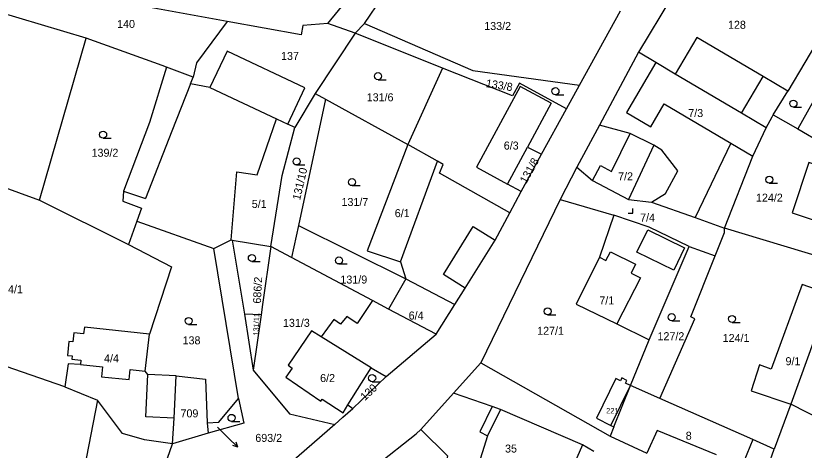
# Model space of a CAD drawing. Extents: x -747333 to -743907, y -1134120 to -1130051.
# Drawn here: x -746528 to -746360.5, y -1132038.3 to -1131946.1 of the extents above; entities that cross this region are included whole.
import ezdxf

# ---------------------------------------------------------------- set-up
doc = ezdxf.new("R2010")
doc.units = 0
for name, color, linetype in [('Hranice parcel', 7, 'Continuous'), ('Parcelní čísla', 7, 'Continuous'), ('Pop  PČ popisy', 7, 'Continuous'), ('Vnitřní kresba', 7, 'Continuous'), ('Značky kultur', 7, 'Continuous')]:
    doc.layers.add(name, color=color, linetype=linetype)

msp = doc.modelspace()

# ---------------------------------------------------------------- linework, layer by layer
at = {"layer": 'Hranice parcel'}
for p, q in [((-746453.89, -1131947.67), (-746438.95, -1131925.52)), ((-746381.8, -1131930.69), (-746395.75, -1131953.81)), ((-746483.07, -1131947.25), (-746560.7, -1131933.13)), ((-746461.71, -1131947.7), (-746454.36, -1131938.7)), ((-746408.25, -1131960.77), (-746399.53, -1131945)), ((-746483.07, -1131947.25), (-746489.62, -1131956.07)), ((-746467.34, -1131950.11), (-746483.07, -1131947.25)), ((-746455.89, -1131949.78), (-746461.71, -1131947.7)), ((-746455.89, -1131949.78), (-746453.89, -1131947.67)), ((-746455.89, -1131949.78), (-746464.41, -1131962.54)), ((-746437.32, -1131957.2), (-746455.89, -1131949.78)), ((-746522.94, -1131985.19), (-746513.04, -1131950.81)), ((-746356.8, -1131949.89), (-746364, -1131962.05)), ((-746352.16, -1131952.55), (-746361.91, -1131970.09)), ((-746466.6, -1131961.34), (-746483.11, -1131953.58)), ((-746395.75, -1131953.81), (-746404.04, -1131969.28)), ((-746489.62, -1131956.07), (-746490.28, -1131959.09)), ((-746490.28, -1131959.09), (-746495.93, -1131956.95)), ((-746437.32, -1131957.2), (-746444.69, -1131973.38)), ((-746411.04, -1131965.81), (-746408.25, -1131960.77)), ((-746464.41, -1131962.54), (-746468.74, -1131969.75)), ((-746464.41, -1131962.54), (-746462.22, -1131963.75)), ((-746367.12, -1131967.06), (-746364, -1131962.05)), ((-746462.22, -1131963.75), (-746467.95, -1131990.55)), ((-746462.22, -1131963.75), (-746444.69, -1131973.38)), ((-746416.31, -1131975.44), (-746411.04, -1131965.81)), ((-746368.62, -1131969.86), (-746367.37, -1131967.53)), ((-746367.37, -1131967.53), (-746367.12, -1131967.06)), ((-746367.12, -1131967.06), (-746361.91, -1131970.09)), ((-746404.04, -1131969.28), (-746408.81, -1131978.18)), ((-746361.91, -1131970.09), (-746334.41, -1131986.06)), ((-746552.82, -1131974.44), (-746522.94, -1131985.19)), ((-746444.69, -1131973.38), (-746453.36, -1131995.97)), ((-746420.64, -1131983.36), (-746416.31, -1131975.44)), ((-746408.81, -1131978.18), (-746412.35, -1131985.06)), ((-746408.81, -1131978.18), (-746405.47, -1131981.01)), ((-746420.64, -1131983.36), (-746423.54, -1131981.79)), ((-746423.09, -1131987.89), (-746420.64, -1131983.36)), ((-746522.94, -1131985.19), (-746504, -1131994.6)), ((-746412.35, -1131985.06), (-746429.19, -1132019.77)), ((-746412.35, -1131985.06), (-746400.99, -1131988.36)), ((-746502.27, -1131989.69), (-746504, -1131994.6)), ((-746502.27, -1131989.69), (-746485.89, -1131995.45)), ((-746400.99, -1131988.36), (-746404.05, -1131997.34)), ((-746467.95, -1131990.55), (-746469.41, -1131997.4)), ((-746467.95, -1131990.55), (-746445.14, -1132001.9)), ((-746354.34, -1131998.17), (-746377.47, -1131991.14)), ((-746485.89, -1131995.45), (-746482.26, -1131993.62)), ((-746482.26, -1131993.62), (-746481.99, -1131993.67)), ((-746481.99, -1131993.67), (-746473.83, -1131995.06)), ((-746481.99, -1131993.67), (-746479.42, -1132009.41)), ((-746480.65, -1132027.32), (-746485.89, -1131995.45)), ((-746469.41, -1131997.4), (-746473.83, -1131995.06)), ((-746393.46, -1132014.85), (-746384.98, -1131995.05)), ((-746384.98, -1131995.05), (-746379.47, -1131997)), ((-746452.2, -1132006.5), (-746469.41, -1131997.4)), ((-746445.14, -1132001.9), (-746448.81, -1132008.32)), ((-746445.14, -1132001.9), (-746434.75, -1132007.36)), ((-746448.81, -1132008.32), (-746452.2, -1132006.5)), ((-746438.69, -1132013.68), (-746448.81, -1132008.32)), ((-746438.69, -1132013.68), (-746434.75, -1132007.36)), ((-746475.88, -1132009.57), (-746479.42, -1132009.41)), ((-746479.42, -1132009.41), (-746477.54, -1132021.27)), ((-746475.88, -1132009.57), (-746477.54, -1132021.27)), ((-746517.52, -1132024.84), (-746547.41, -1132014.55)), ((-746449.32, -1132022.63), (-746438.69, -1132013.68)), ((-746397.45, -1132024.58), (-746393.46, -1132014.85)), ((-746435.02, -1132026.19), (-746429.19, -1132019.77)), ((-746429.19, -1132019.77), (-746401.77, -1132035.28)), ((-746456.4, -1132029.43), (-746449.32, -1132022.63)), ((-746517.52, -1132024.84), (-746510.62, -1132027.7)), ((-746400.98, -1132033.31), (-746397.45, -1132024.58)), ((-746391.22, -1132027.33), (-746397.45, -1132024.58)), ((-746441.94, -1132033.89), (-746435.02, -1132026.19)), ((-746426.8, -1132029.03), (-746435.02, -1132026.19)), ((-746510.62, -1132027.7), (-746513.48, -1132042.23)), ((-746457.44, -1132028.67), (-746456.4, -1132029.43)), ((-746363.4, -1132028.51), (-746366.94, -1132038.04)), ((-746352.22, -1132034.3), (-746363.4, -1132028.51)), ((-746487.32, -1132032.51), (-746487.1, -1132034.68)), ((-746460.24, -1132032.84), (-746481.01, -1132050.82)), ((-746400.98, -1132033.31), (-746401.77, -1132035.28)), ((-746401.6, -1132033.01), (-746400.98, -1132033.31)), ((-746487.1, -1132034.68), (-746494.65, -1132036.93)), ((-746401.77, -1132035.28), (-746393.96, -1132038.89))]:
    msp.add_line(p, q, dxfattribs=at)
for points in [[(-746513.04, -1131950.81), (-746536.83, -1131943.73), (-746543.47, -1131941.76)], [(-746461.71, -1131947.7), (-746466.99, -1131948.14), (-746467.34, -1131950.11)], [(-746453.89, -1131947.67), (-746430.93, -1131957.68), (-746408.25, -1131960.77)], [(-746495.93, -1131956.95), (-746496.86, -1131956.6), (-746513.04, -1131950.81)], [(-746383.37, -1131950.7), (-746387.94, -1131958.43), (-746392.06, -1131955.99), (-746395.75, -1131953.81)], [(-746364, -1131962.05), (-746369.24, -1131958.95), (-746383.37, -1131950.7)], [(-746483.11, -1131953.58), (-746486.74, -1131961.29), (-746490.84, -1131960.52), (-746490.28, -1131959.09)], [(-746495.93, -1131956.95), (-746499.59, -1131968.72), (-746505.1, -1131983.28), (-746505.25, -1131985.42), (-746501.26, -1131986.91), (-746502.27, -1131989.69)], [(-746411.04, -1131965.81), (-746421.04, -1131960.39), (-746422.49, -1131963.07), (-746437.32, -1131957.2)], [(-746468.74, -1131969.75), (-746470.23, -1131969.05), (-746466.6, -1131961.34)], [(-746473.83, -1131995.06), (-746471.42, -1131979.96), (-746468.74, -1131969.75)], [(-746392.96, -1131985.62), (-746390.02, -1131983.77), (-746387.42, -1131978.99), (-746390.76, -1131974.61), (-746392.46, -1131973.55), (-746397.49, -1131971.05), (-746404.04, -1131969.28)], [(-746377.47, -1131991.14), (-746371.48, -1131975.87), (-746368.62, -1131969.86)], [(-746423.09, -1131987.89), (-746437.98, -1131979.44), (-746437.18, -1131977.66), (-746438.41, -1131976.96), (-746444.69, -1131973.38)], [(-746423.54, -1131981.79), (-746419.29, -1131973.93), (-746416.31, -1131975.44)], [(-746351.98, -1131979.75), (-746359.57, -1131977.21), (-746363.14, -1131987.9), (-746352.22, -1131991.54), (-746351.68, -1131989.88), (-746350.17, -1131989.11), (-746349.66, -1131987.58), (-746350.41, -1131986.06), (-746349.86, -1131984.42), (-746353.17, -1131983.31), (-746351.98, -1131979.75)], [(-746405.47, -1131981.01), (-746397.86, -1131985.09), (-746392.96, -1131985.62)], [(-746392.96, -1131985.62), (-746383.74, -1131988.91), (-746377.47, -1131991.14)], [(-746434.75, -1132007.36), (-746432.53, -1132003.87), (-746426.16, -1131993.7), (-746423.09, -1131987.89)], [(-746384.98, -1131995.05), (-746393.44, -1131990.91), (-746400.99, -1131988.36)], [(-746379.47, -1131997), (-746377.51, -1131992.07), (-746377.47, -1131991.14)], [(-746504, -1131994.6), (-746494.93, -1131999.39), (-746499.57, -1132013.64)], [(-746473.83, -1131995.06), (-746475.57, -1132007.36), (-746475.88, -1132009.57)], [(-746453.36, -1131995.97), (-746446.26, -1131998.3), (-746445.14, -1132001.9)], [(-746404.05, -1131997.34), (-746409, -1132007.27), (-746400.37, -1132011.48), (-746393.46, -1132014.85)], [(-746391.22, -1132027.33), (-746383.75, -1132010.4), (-746384.66, -1132010), (-746379.47, -1131997)], [(-746354.34, -1131998.17), (-746356.76, -1132004.57), (-746361.01, -1132003.1), (-746367.57, -1132021.06), (-746370.07, -1132020.2), (-746371.84, -1132025.7), (-746363.4, -1132028.51)], [(-746452.2, -1132006.5), (-746455.47, -1132011.39), (-746457.7, -1132009.89), (-746459.01, -1132011.55), (-746460.4, -1132010.51), (-746463.13, -1132014.2), (-746465.2, -1132012.95), (-746470.12, -1132020.21), (-746469.3, -1132020.9), (-746470.59, -1132022.75), (-746463.17, -1132027.85), (-746462.91, -1132027.46), (-746458.46, -1132030.36), (-746457.44, -1132028.67)], [(-746513.55, -1132013.58), (-746515.63, -1132013.35), (-746515.84, -1132015.29), (-746516.68, -1132015.19), (-746517, -1132018.17), (-746516.01, -1132018.28), (-746516.08, -1132018.96), (-746514.15, -1132019.17), (-746514.25, -1132020.11)], [(-746499.57, -1132013.64), (-746513.39, -1132012.14), (-746513.55, -1132013.58)], [(-746493.92, -1132022.53), (-746499.94, -1132022.24), (-746500.46, -1132021.48), (-746499.57, -1132013.64)], [(-746514.25, -1132020.11), (-746516.85, -1132019.93), (-746517.52, -1132024.84)], [(-746477.54, -1132021.27), (-746469.81, -1132030.6), (-746460.24, -1132032.84)], [(-746457.44, -1132028.67), (-746452.47, -1132020.78), (-746449.32, -1132022.63)], [(-746494.65, -1132036.93), (-746494.35, -1132031.46), (-746493.92, -1132022.53)], [(-746493.92, -1132022.53), (-746487.66, -1132023.23), (-746487.32, -1132032.51)], [(-746397.45, -1132024.58), (-746398.5, -1132024.07), (-746398.22, -1132023.48), (-746399.27, -1132022.95), (-746399.56, -1132023.55), (-746400.54, -1132023.07), (-746404.66, -1132031.52), (-746401.6, -1132033.01)], [(-746494.65, -1132036.93), (-746500.61, -1132036.09), (-746505.29, -1132034.76), (-746510.62, -1132027.7)], [(-746487.32, -1132032.51), (-746484.84, -1132032.33), (-746480.65, -1132027.32)], [(-746480.65, -1132027.32), (-746479.53, -1132032.56), (-746487.1, -1132034.68)], [(-746366.94, -1132038.04), (-746371.46, -1132036.05), (-746391.22, -1132027.33)], [(-746460.24, -1132032.84), (-746458.5, -1132031.29), (-746456.4, -1132029.43)], [(-746426.8, -1132029.03), (-746429.42, -1132034.4), (-746427.78, -1132035.27), (-746430.06, -1132042.48)], [(-746405.2, -1132038.56), (-746407.63, -1132037.16), (-746425.03, -1132029.66), (-746426.8, -1132029.03)], [(-746451.35, -1132041.44), (-746442.97, -1132034.81), (-746441.94, -1132033.89)], [(-746441.94, -1132033.89), (-746436.31, -1132039.52), (-746440.38, -1132057.72)], [(-746498.18, -1132046.57), (-746497.26, -1132044.25), (-746494.65, -1132036.93)], [(-746374.84, -1132047.38), (-746369.36, -1132044.89), (-746366.94, -1132038.04)]]:
    msp.add_lwpolyline(points, dxfattribs=at)
at = {"layer": 'Pop  PČ popisy'}
for p, q in [((-746485.16, -1132033.41), (-746482.94, -1132035.56)), ((-746482.94, -1132035.56), (-746480.781, -1132037.645)), ((-746480.781, -1132037.645), (-746481.154, -1132036.589)), ((-746480.781, -1132037.645), (-746481.85, -1132037.309))]:
    msp.add_line(p, q, dxfattribs=at)
at = {"layer": 'Vnitřní kresba'}
for p, q in [((-746392.06, -1131955.99), (-746398.27, -1131966.61)), ((-746373.86, -1131966.76), (-746387.94, -1131958.43)), ((-746373.86, -1131966.76), (-746369.24, -1131958.95)), ((-746490.84, -1131960.52), (-746494.8, -1131970.55)), ((-746486.74, -1131961.29), (-746472.6, -1131967.94)), ((-746420.84, -1131961.07), (-746430.12, -1131978.23)), ((-746414.26, -1131964.63), (-746420.84, -1131961.07)), ((-746414.26, -1131964.63), (-746419.29, -1131973.93)), ((-746393.11, -1131969.63), (-746390.26, -1131964.74)), ((-746390.26, -1131964.74), (-746376.15, -1131973.1)), ((-746476.68, -1131979.81), (-746472.6, -1131967.94)), ((-746472.6, -1131967.94), (-746470.23, -1131969.05)), ((-746398.27, -1131966.61), (-746393.11, -1131969.63)), ((-746368.62, -1131969.86), (-746373.86, -1131966.76)), ((-746494.8, -1131970.55), (-746500.43, -1131984.82)), ((-746401.49, -1131979.09), (-746397.49, -1131971.05)), ((-746376.15, -1131973.1), (-746383.74, -1131988.91)), ((-746376.15, -1131973.1), (-746371.48, -1131975.87)), ((-746392.46, -1131973.55), (-746397.86, -1131985.09)), ((-746446.26, -1131998.3), (-746438.41, -1131976.96)), ((-746430.12, -1131978.23), (-746423.54, -1131981.79)), ((-746405.47, -1131981.01), (-746403.78, -1131977.86)), ((-746403.78, -1131977.86), (-746401.49, -1131979.09)), ((-746482.26, -1131993.62), (-746481, -1131979.2)), ((-746481, -1131979.2), (-746476.68, -1131979.81)), ((-746505.1, -1131983.28), (-746500.43, -1131984.82)), ((-746437.16, -1132000.97), (-746430.81, -1131990.79)), ((-746430.81, -1131990.79), (-746426.16, -1131993.7)), ((-746396.07, -1131996.26), (-746393.75, -1131991.54)), ((-746393.75, -1131991.54), (-746385.96, -1131995.34)), ((-746402.65, -1131998.04), (-746401.71, -1131996.16)), ((-746401.71, -1131996.16), (-746396.39, -1131998.81)), ((-746388.24, -1132000.05), (-746396.07, -1131996.26)), ((-746385.96, -1131995.34), (-746388.24, -1132000.05)), ((-746404.05, -1131997.34), (-746402.65, -1131998.04)), ((-746396.39, -1131998.81), (-746397.32, -1132000.69)), ((-746432.53, -1132003.87), (-746437.16, -1132000.97)), ((-746395.34, -1132001.68), (-746400.37, -1132011.48)), ((-746397.32, -1132000.69), (-746395.34, -1132001.68)), ((-746354.99, -1132005.18), (-746363.4, -1132028.51)), ((-746452.47, -1132020.78), (-746463.13, -1132014.2)), ((-746514.25, -1132020.11), (-746509.52, -1132020.58)), ((-746509.52, -1132020.58), (-746509.73, -1132022.72)), ((-746503.91, -1132023.3), (-746503.69, -1132021.16)), ((-746503.69, -1132021.16), (-746500.46, -1132021.48)), ((-746509.73, -1132022.72), (-746503.91, -1132023.3)), ((-746500.37, -1132031.17), (-746499.94, -1132022.24)), ((-746401.6, -1132033.01), (-746397.45, -1132024.58)), ((-746425.03, -1132029.66), (-746427.78, -1132035.27)), ((-746494.35, -1132031.46), (-746500.37, -1132031.17)), ((-746391.76, -1132034.12), (-746393.96, -1132038.89)), ((-746379.18, -1132039.26), (-746391.76, -1132034.12)), ((-746371.46, -1132036.05), (-746375.91, -1132046.94)), ((-746407.63, -1132037.16), (-746409.79, -1132042.16))]:
    msp.add_line(p, q, dxfattribs=at)
at = {"layer": 'Značky kultur'}
for p, q in [((-746451.043, -1131959.63), (-746449.293, -1131959.63)), ((-746413.373, -1131962.82), (-746411.623, -1131962.82)), ((-746362.843, -1131965.46), (-746361.093, -1131965.46)), ((-746509.423, -1131972.05), (-746507.673, -1131972.05)), ((-746468.333, -1131977.73), (-746466.583, -1131977.73)), ((-746456.563, -1131982.12), (-746454.813, -1131982.12)), ((-746367.963, -1131981.61), (-746366.213, -1131981.61)), ((-746397.941, -1131988), (-746396.94, -1131988)), ((-746396.94, -1131988), (-746396.94, -1131987)), ((-746477.823, -1131998.25), (-746476.073, -1131998.25)), ((-746459.333, -1131998.75), (-746457.583, -1131998.75)), ((-746415.033, -1132009.56), (-746413.283, -1132009.56)), ((-746491.263, -1132011.6), (-746489.513, -1132011.6)), ((-746388.693, -1132010.79), (-746386.943, -1132010.79)), ((-746375.873, -1132011.17), (-746374.123, -1132011.17)), ((-746452.293, -1132023.74), (-746450.543, -1132023.74)), ((-746482.143, -1132032.18), (-746480.393, -1132032.18))]:
    msp.add_line(p, q, dxfattribs=at)
for centre in [(-746451.043, -1131958.88), (-746413.373, -1131962.07), (-746362.843, -1131964.71), (-746509.423, -1131971.3), (-746468.333, -1131976.98), (-746456.563, -1131981.37), (-746367.963, -1131980.86), (-746477.823, -1131997.5), (-746459.333, -1131998), (-746415.033, -1132008.81), (-746388.693, -1132010.04), (-746375.873, -1132010.42), (-746491.263, -1132010.85), (-746452.293, -1132022.99), (-746482.143, -1132031.43)]:
    msp.add_circle(centre, 0.75, dxfattribs=at)

# ---------------------------------------------------------------- texts
at = {"layer": 'Parcelní čísla'}
for s, height, p in [('140', 1.7, (-746506.444, -1131948.65)), ('133/2', 1.7, (-746428.49, -1131949.08)), ('128', 1.7, (-746376.73, -1131948.82)), ('137', 1.7, (-746471.634, -1131955.44)), ('131/6', 1.7, (-746453.45, -1131964.22)), ('7/3', 1.7, (-746385.17, -1131967.56)), ('6/3', 1.7, (-746424.35, -1131974.47)), ('139/2', 1.7, (-746511.87, -1131975.99)), ('7/2', 1.7, (-746400.07, -1131981)), ('131/7', 1.7, (-746458.8, -1131986.44)), ('124/2', 1.7, (-746370.79, -1131985.53)), ('5/1', 1.7, (-746477.85, -1131986.86)), ('6/1', 1.7, (-746447.49, -1131988.81)), ('7/4', 1.7, (-746395.39, -1131989.75)), ('131/9', 1.7, (-746459.03, -1132002.91)), ('224/1', 1.7, (-746532.14, -1132004.97)), ('7/1', 1.7, (-746404.06, -1132007.34)), ('6/4', 1.7, (-746444.54, -1132010.55)), ('131/3', 1.7, (-746471.23, -1132012.1)), ('127/1', 1.7, (-746417.26, -1132013.79)), ('127/2', 1.7, (-746391.7, -1132014.94)), ('138', 1.7, (-746492.54, -1132015.82)), ('124/1', 1.7, (-746377.87, -1132015.32)), ('4/4', 1.7, (-746509.22, -1132019.64)), ('9/1', 1.7, (-746364.52, -1132020.24)), ('6/2', 1.7, (-746463.34, -1132023.82)), ('709', 1.7, (-746492.984, -1132031.32)), ('221', 1.14, (-746402.6, -1132030.48)), ('693/2', 1.7, (-746477.1, -1132036.53)), ('8', 1.7, (-746385.71, -1132036.06)), ('35', 1.7, (-746424.07, -1132038.79))]:
    msp.add_text(s, height=height, dxfattribs=at).set_placement(p)
for s, height, rotation, p in [('133/8', 1.7, 351, (-746428.232, -1131961.189)), ('131/8', 1.7, 61, (-746419.566, -1131981.812)), ('131/10', 1.7, 77, (-746467.601, -1131985.311)), ('686/2', 1.7, 87, (-746475.931, -1132007.204)), ('131/11', 1.14, 88, (-746476.41, -1132013.989)), ('130', 1.7, 43, (-746453.84, -1132027.871))]:
    msp.add_text(s, height=height, rotation=rotation, dxfattribs=at).set_placement(p)

doc.saveas('drawing.dxf')
